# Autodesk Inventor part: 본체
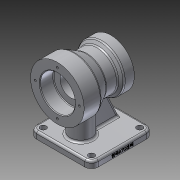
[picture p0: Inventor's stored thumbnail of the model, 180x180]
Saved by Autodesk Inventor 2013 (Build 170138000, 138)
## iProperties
Created: 2019-01
Part Number: 본체
Material: 알루미늄 6061
Document SubType Name: Modeling
Designer: hana-cad23
Density: 2.71 g/cm^3
Mass: 911.577 g
Surface Area: 600.084 cm^2
Volume: 336.375 cm^3
Author: hana-cad23
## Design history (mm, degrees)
sketch "스케치1"
  geometry: L1 (-40, 0)-(40, 0); L2 (40, 0)-(40, 35); L3 (40, 35)-(25, 35); L4 (-40, 0)-(-40, 40); L5 (-40, 40)-(-15, 40); L6 (-15, 40)-(3.394, 29.38); L7 (3.394, 29.38)-(20.284, 29.38); L8 (20.284, 29.38)-(25, 35); 2 further points
  constraints: 16 end point, 3 perpendicular, 1 coincident, 1 horizontal, 1 midpoint, 1 parallel
  dimensions: "d0" = 80 distance of L1.start L1.end; "d11" = 15 distance of L2.end L3.end; "d13" = 25 distance of L4.end L5.end; "d14" = 30 deg angle of L5 L6; "d15" = 50 deg angle of L7 L8; "d16" = 80 diameter of L5 L1; "d18" = 70 diameter of L3 L1; "d19" = 16.89004 distance of L6.end L7.end
revolve "회전1" sketch "스케치1" stored, may be unused: angle "d20" = 90 deg
sketch "스케치2"
  geometry: L1 (-40, 35)-(-40, -35) reference; L2 (40, 40)-(40, -40) reference; L3 (40, 0)-(-40, 0); L4 (40, 0)-(40, 26); L5 (40, 26)-(21, 26); L6 (20, 25)-(20, 16); L7 (20, 16)-(-23, 16); L8 (-23, 16)-(-23, 19.4); L9 (-23.6, 20)-(-40, 20); L10 (-40, 20)-(-40, 0); A1 r 1 centre (21, 25) between (21, 26) and (20, 25); A2 r 0.6 centre (-23.6, 19.4) between (-23, 19.4) and (-23.6, 20); 3 further points
  constraints: 16 end point, 6 point on line, 4 point on circle, 4 tangent, 3 perpendicular, 2 centre point, 2 midpoint, 2 parallel, 1 collinear
  dimensions: "d21" = 26 distance of L3.start L4.end; "d22" = 20 distance of L4.end point (20, 26); "d23" = 10 distance of point (20, 26) L6.end; "d24" = 43 distance of L6.end L7.end; "d25" = 4 distance of L7.end point (-23, 20); "d26" = 1 radius of A1; "d27" = 0.6 radius of A2
revolve "회전2" sketch "스케치2" stored, may be unused: angle "d28" = 90 deg
node "작업 평면1"
sketch "스케치3"
  geometry: L1 (-40, -40)-(-40, 40) reference; L2 (-35, -46)-(57, -46); L3 (57, -46)-(57, 46); L4 (57, 46)-(-35, 46); L5 (-35, 46)-(-35, -46); L6 (-35, -46)-(57, 46); L7 (57, -46)-(-35, 46); 4 further points
  constraints: 12 end point, 4 midpoint, 2 parallel, 1 horizontal, 1 horizontal alignment, 1 perpendicular
  dimensions: "d33" = 92 distance of L3.end L4.end; "d35" = 92 distance of L2.end L3.end; "d36" = 5 distance between parallel lines of L1 L5
extrude "돌출1" join sketch "스케치3" distance "d37" = 10; taper "d38" = 0 deg
sketch "스케치4"
  geometry: L1 (35, -46)-(35, 46) reference; C1 r 16 at (5, 0); 2 further points
  constraints: 1 centre point, 1 horizontal alignment, 1 midpoint
  dimensions: "d39" = 32 diameter of C1; "d41" = 30 distance from line of L1 C1.centre
extrude "돌출2" join sketch "스케치4" stored distance "d42" = 10; taper "d43" = 0 deg
sketch "스케치5"
  geometry: L1 (-57, 80)-(-57, 70) reference; L2 (-47, 70)-(-26.137, 25.258); L3 (35, 70)-(-57, 70) reference; L4 (-47, 70)-(-6.839, 70); L5 (-6.839, 25.258)-(-26.137, 25.258); L6 (-6.839, 70)-(-6.839, 25.258); 1 further point
  constraints: 8 end point, 1 parallel, 1 perpendicular, 1 point on line
  dimensions: "d45" = 25 deg angle of L1 L2; "d46" = 10 distance from line of L1 L2.start; "d47" = 40.161 distance of L2.start L4.end; "d48" = 44.74174 distance of L4.end L5.start; "d49" = 19.29758 distance of L5.start L2.end
extrude "돌출3" join sketch "스케치5" stored distance "d50" = 10; taper "d51" = 0 deg
fillet "모깎기1" dims "d52" = 10
sketch "스케치6"
  geometry: C1 r 4.5 at (-47, 36); C2 r 4.5 at (-47, -36); C3 r 4.5 at (25, 36); C4 r 4.5 at (25, -36); A1 r 10 centre (25, 36) between (35, 36) and (25, 46) reference; A2 r 10 centre (-47, 36) between (-47, 46) and (-57, 36) reference; A3 r 10 centre (-47, -36) between (-57, -36) and (-47, -46) reference; A4 r 10 centre (25, -36) between (25, -46) and (35, -36) reference; 1 further point
  constraints: 4 centre point, 4 coincident
  dimensions: "d53" = 9 diameter of C1; "d54" = 9 diameter of C2; "d55" = 9 diameter of C3; "d56" = 9 diameter of C4
extrude "돌출4" cut sketch "스케치6" stored distance "d57" = 10; taper "d58" = 0 deg
fillet "모깎기2" dims "d59" = 3
fillet "모깎기3" dims "d60" = 3
fillet "모깎기4" dims "d61" = 3
sketch "스케치7"
  geometry: C1 r 26 at (0, 0) reference; 1 further point
  constraints: 1 vertical alignment
  dimensions: "d62" = 33 distance of C1.centre point (0, -33)
hole "구멍1" sketch "스케치7" at (0, -33) diameter "d63" = 3.242; stored, may be unused: countersink angle "d67" = 90 deg, drill point angle "d69" = 118 deg; dims "d64" = 9, "d65" = 4, "d66" = 2, "d68" = 11
sketch "스케치8"
  geometry: C1 r 20 at (0, 0) reference; 1 further point
  constraints: 1 vertical alignment
  dimensions: "d73" = 27.5 distance of point (0, -27.5) C1.centre
hole "구멍2" sketch "스케치8" at (0, -27.5) diameter "d74" = 3.242; stored, may be unused: countersink angle "d78" = 90 deg, drill point angle "d80" = 118 deg; dims "d75" = 9, "d76" = 4, "d77" = 2, "d79" = 11
chamfer "모따기1" distance "d84" = 1; stored, may be unused: second distance "d85" = 2, angle "d86" = 45 deg
node "작업 평면2"
sketch "스케치9"
  geometry: L1 (35, 73)-(35, 80) reference; L2 (-47, 80)-(25, 80) reference; L3 (-57, 80)-(-47, 80) reference; 2 further points
  constraints: 1 other
  dimensions: "d88" = 46 distance from line of point (-11, 76) L1; "d89" = 4 distance from line of L3 point (-11, 76)
feature "엠보싱1" sketch "스케치9" dims "d0" = 80, "d11" = 15, "d13" = 25, "d14" = 30 deg, "d15" = 50 deg, "d16" = 80, "d18" = 70, "d19" = 16.89004, "d90" = 0.5, "d91" = 0
node "솔리드1"
pattern_circular "원형 패턴1" dims angle "d71" = 360 deg
pattern_circular "원형 패턴2" dims angle "d82" = 360 deg
other parameters: "d87" = 62.5
